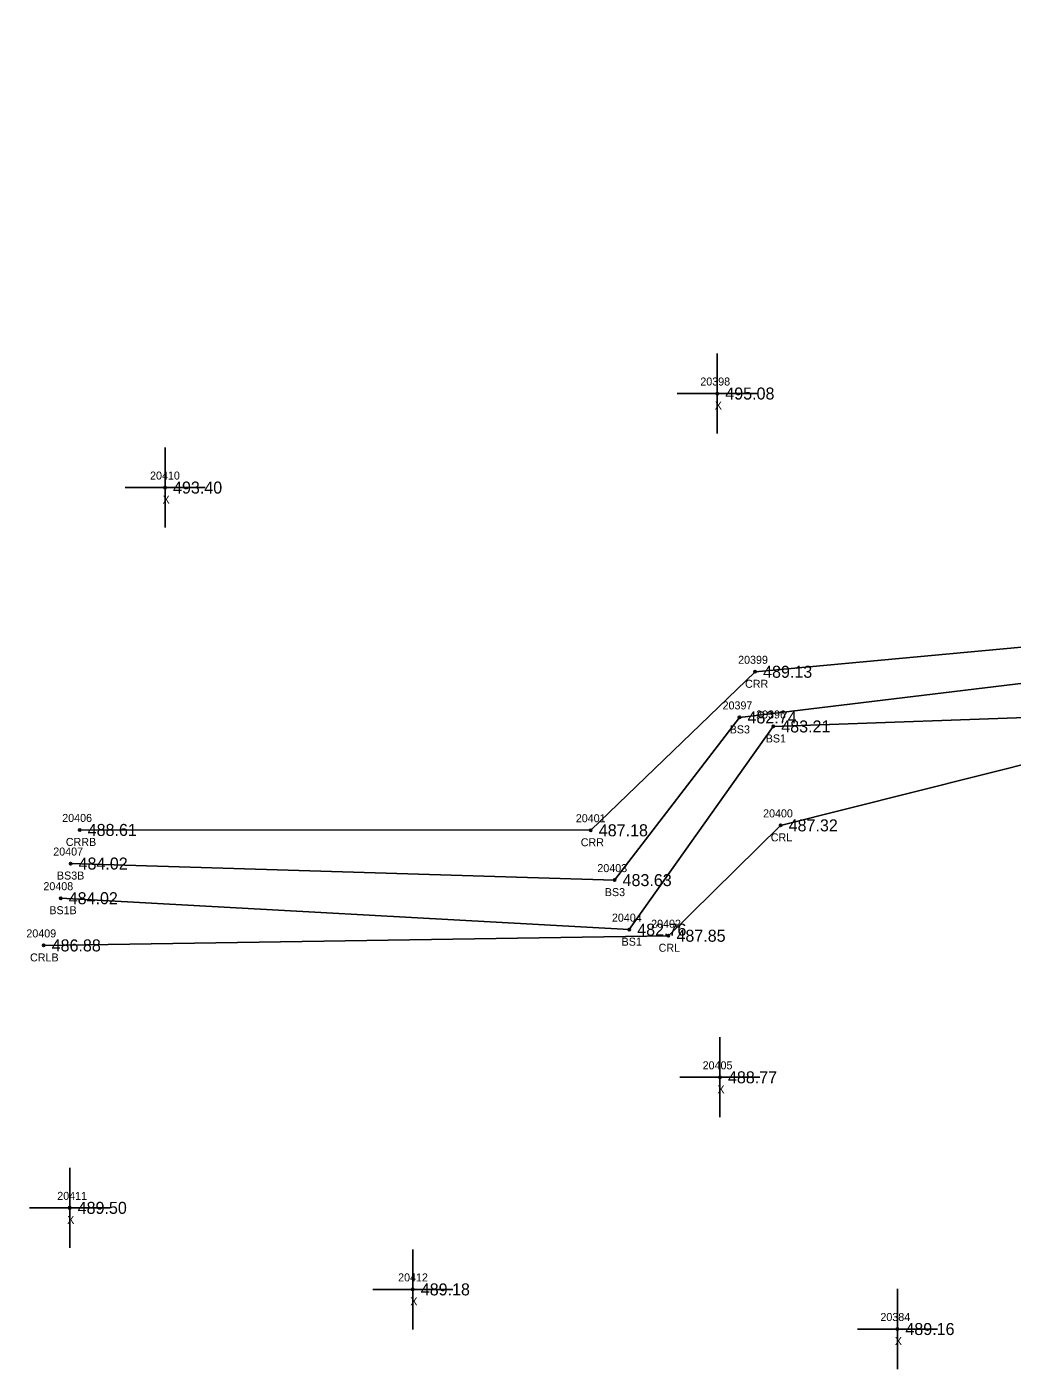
# Model space of a CAD drawing. Extents: x 1649406 to 1650436, y 896752 to 898178.
# Drawn here: x 1649428.8 to 1649551.9, y 897284.6 to 897452.8 of the extents above; entities that cross this region are included whole.
import ezdxf

# ---------------------------------------------------------------- set-up
doc = ezdxf.new("R2010")
doc.units = 0
for name, color, linetype in [('RD_DTM_BkLn2', 7, 'Continuous'), ('RD_DTM_BkLn_txCode', 7, 'Continuous'), ('RD_EX_H2O', 7, 'Continuous'), ('RD_EX_H2O_txCode', 7, 'Continuous'), ('RD_EX_Misc', 7, 'Continuous'), ('RD_EX_Misc_txCode', 7, 'Continuous'), ('RD_EX_TX_H2O_ELEV', 7, 'Continuous'), ('RD_EX_TX_Misc_ELEV', 7, 'Continuous'), ('RD_SMD_Locator', 7, 'Continuous')]:
    doc.layers.add(name, color=color, linetype=linetype)

msp = doc.modelspace()

# ---------------------------------------------------------------- linework, layer by layer
at = {"layer": 'RD_DTM_BkLn2'}
for points in [[(1649735.32, 897452.32), (1649735.42, 897430.71), (1649726.93, 897424.04), (1649733.64, 897412.51), (1649739.22, 897406.36), (1649710.88, 897394.12), (1649696.6, 897378.36), (1649634.62, 897385.73), (1649610.45, 897366.7), (1649591.79, 897363.75), (1649561.2, 897371.75), (1649517.81, 897366.5), (1649502.21, 897346.17), (1649434.27, 897348.24)], [(1649581.25, 897284.57), (1649586.52, 897319.78), (1649588.4, 897358.66), (1649559.43, 897366.69), (1649522.03, 897365.37), (1649504.04, 897339.98), (1649433.04, 897343.91)]]:
    msp.add_lwpolyline(points, dxfattribs=at)
at = {"layer": 'RD_EX_H2O'}
for points in [[(1649733.89, 897452.78), (1649733.23, 897431.68), (1649726.08, 897424.3), (1649730.38, 897411.38), (1649709.93, 897395.57), (1649696.43, 897381.39), (1649633.87, 897388.98), (1649608.54, 897369.49), (1649592.36, 897367.34), (1649564.26, 897376.33), (1649519.76, 897372.2), (1649499.24, 897352.4), (1649435.41, 897352.44)], [(1649577.82, 897286.19), (1649581.78, 897320.47), (1649585.44, 897357.5), (1649556.22, 897361.38), (1649522.95, 897353.01), (1649508.94, 897339.22), (1649430.91, 897338.01)]]:
    msp.add_lwpolyline(points, dxfattribs=at)
at = {"layer": 'RD_EX_Misc'}
for p, q in [((1649515.04, 897401.97), (1649515.04, 897411.97)), ((1649510.04, 897406.97), (1649520.04, 897406.97)), ((1649446.07, 897390.22), (1649446.07, 897400.22)), ((1649441.07, 897395.22), (1649451.07, 897395.22)), ((1649515.37, 897316.53), (1649515.37, 897326.53)), ((1649510.37, 897321.53), (1649520.37, 897321.53)), ((1649434.16, 897300.22), (1649434.16, 897310.22)), ((1649429.16, 897305.22), (1649439.16, 897305.22)), ((1649477.01, 897290.03), (1649477.01, 897300.03)), ((1649472.01, 897295.03), (1649482.01, 897295.03)), ((1649537.53, 897285.08), (1649537.53, 897295.08)), ((1649532.53, 897290.08), (1649542.53, 897290.08))]:
    msp.add_line(p, q, dxfattribs=at)
at = {"layer": 'RD_SMD_Locator'}
for centre in [(1649515.04, 897406.97), (1649446.07, 897395.22), (1649519.76, 897372.2), (1649517.81, 897366.5), (1649522.03, 897365.37), (1649522.95, 897353.01), (1649435.41, 897352.44), (1649499.24, 897352.4), (1649434.27, 897348.24), (1649502.21, 897346.17), (1649433.04, 897343.91), (1649504.04, 897339.98), (1649508.94, 897339.22), (1649430.91, 897338.01), (1649515.37, 897321.53), (1649434.16, 897305.22), (1649477.01, 897295.03), (1649537.53, 897290.08)]:
    msp.add_circle(centre, 0.15, dxfattribs=at)

# ---------------------------------------------------------------- texts
at = {"layer": 'RD_DTM_BkLn_txCode'}
for s, p in [('20397', (1649515.7, 897367.5)), ('20396', (1649519.89, 897366.37)), ('BS3', (1649516.59, 897364.5)), ('BS1', (1649521.09, 897363.37)), ('20407', (1649432.11, 897349.24)), ('20403', (1649500.06, 897347.17)), ('BS3B', (1649432.57, 897346.24)), ('20408', (1649430.88, 897344.91)), ('BS3', (1649500.99, 897344.17)), ('BS1B', (1649431.62, 897341.91)), ('20404', (1649501.88, 897340.98)), ('BS1', (1649503.09, 897337.98))]:
    msp.add_text(s, height=1, dxfattribs=at).set_placement(p)
at = {"layer": 'RD_EX_H2O_txCode'}
for s, p in [('20399', (1649517.64, 897373.2)), ('CRR', (1649518.51, 897370.2)), ('20400', (1649520.76, 897354.01)), ('20406', (1649433.23, 897353.44)), ('20401', (1649497.37, 897353.4)), ('CRRB', (1649433.68, 897350.44)), ('CRR', (1649497.99, 897350.4)), ('CRL', (1649521.72, 897351.01)), ('20402', (1649506.78, 897340.22)), ('20409', (1649428.75, 897339.01)), ('CRL', (1649507.71, 897337.22)), ('CRLB', (1649429.21, 897336.01))]:
    msp.add_text(s, height=1, dxfattribs=at).set_placement(p)
at = {"layer": 'RD_EX_Misc_txCode'}
for s, p in [('20398', (1649512.92, 897407.97)), ('X', (1649514.72, 897404.97)), ('20410', (1649444.2, 897396.22)), ('X', (1649445.76, 897393.22)), ('20405', (1649513.21, 897322.53)), ('X', (1649515.05, 897319.53)), ('20411', (1649432.61, 897306.22)), ('X', (1649433.85, 897303.22)), ('20412', (1649475.18, 897296.03)), ('X', (1649476.7, 897293.03)), ('20384', (1649535.41, 897291.08)), ('X', (1649537.21, 897288.08))]:
    msp.add_text(s, height=1, dxfattribs=at).set_placement(p)
at = {"layer": 'RD_EX_TX_H2O_ELEV'}
for s, p in [('489.13', (1649520.76, 897371.45)), ('488.61', (1649436.41, 897351.69)), ('487.18', (1649500.24, 897351.65)), ('487.32', (1649523.95, 897352.26)), ('487.85', (1649509.94, 897338.47)), ('486.88', (1649431.91, 897337.26))]:
    msp.add_text(s, height=1.5, dxfattribs=at).set_placement(p)
at = {"layer": 'RD_EX_TX_Misc_ELEV'}
for s, p in [('495.08', (1649516.04, 897406.22)), ('493.40', (1649447.07, 897394.47)), ('482.74', (1649518.81, 897365.75)), ('483.21', (1649523.03, 897364.62)), ('484.02', (1649435.27, 897347.49)), ('483.63', (1649503.21, 897345.42)), ('484.02', (1649434.04, 897343.16)), ('482.76', (1649505.04, 897339.23)), ('488.77', (1649516.37, 897320.78)), ('489.50', (1649435.16, 897304.47)), ('489.18', (1649478.01, 897294.28)), ('489.16', (1649538.53, 897289.33))]:
    msp.add_text(s, height=1.5, dxfattribs=at).set_placement(p)

doc.saveas('drawing.dxf')
